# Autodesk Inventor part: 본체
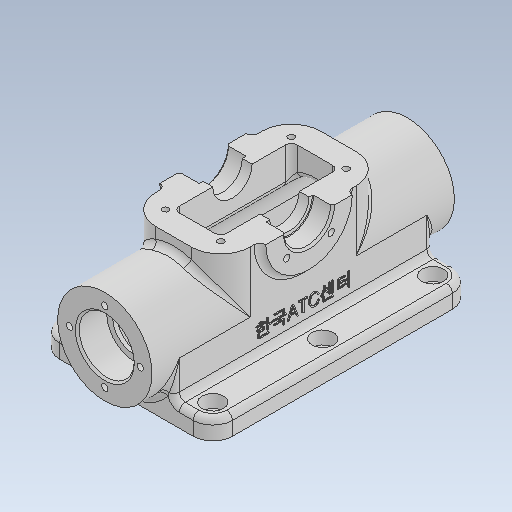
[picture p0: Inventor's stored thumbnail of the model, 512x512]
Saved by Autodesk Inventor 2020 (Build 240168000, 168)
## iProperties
Created: 2024-07
Part Number: 본체
Material: 일반
Document SubType Name: Modeling
Designer: oem
Density: 1 g/cm^3
Appearance: 기본값
Mass: 204.277 g
Surface Area: 612.262 cm^2
Volume: 204.277 cm^3
Sending System: Autodesk Inventor 2025
Preprocessor: ST-DEVELOPER v20
Author: jhkim
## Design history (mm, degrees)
feature "솔리드1"
node "솔리드2"
